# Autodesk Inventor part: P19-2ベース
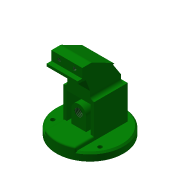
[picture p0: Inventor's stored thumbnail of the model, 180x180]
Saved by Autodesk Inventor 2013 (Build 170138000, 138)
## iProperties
Created: 2008-07
Part Number: P19-2ベース
Document SubType Name: Modeling
Designer: y-shimohigashi
Density: 1 g/cm^3
Stock Number: P19-2ベース
Material: 一般
Author: y-shimohigashi
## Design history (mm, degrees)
sketch "スケッチ2"
  geometry: C1 r 65 at (0, 0); 1 further point
  constraints: 1 centre point, 1 coincident
  dimensions: "d0" = 130 diameter of C1
extrude "押し出し1" new body sketch "スケッチ2" distance "d1" = 15; taper "d2" = 0 deg
sketch "スケッチ3"
  geometry: L1 (-65, 15)-(65, 15) reference; L2 (43, 15)-(43, 80); L3 (43, 80)-(38, 80); L4 (38, 80)-(38, 93); L5 (38, 93)-(16, 127); L6 (16, 127)-(-27, 149); L7 (-27, 149)-(-45, 149); L8 (-45, 149)-(-45, 131); L9 (-45, 131)-(-54, 131); L10 (-54, 131)-(-54, 126); L11 (-54, 126)-(-44, 126); L12 (-44, 126)-(-31, 119); L13 (-31, 119)-(-22, 95); L14 (-22, 95)-(-22, 15); L15 (-22, 15)-(43, 15); 1 further point
  constraints: 28 end point, 6 parallel, 3 perpendicular, 2 point on line, 1 collinear
  dimensions: "d3" = 43 distance from line of L2 point (0, 0); "d4" = 65 distance of L2.start L2.end; "d5" = 13 distance of L3.end L4.end; "d6" = 34 vertical distance of L4.end L5.end; "d7" = 22 vertical distance of L5.end L6.end; "d8" = 5 distance of L2.end L3.end; "d9" = 22 horizontal distance of L4.end L5.end; "d10" = 43 horizontal distance of L5.end L6.end; "d11" = 18 distance of L6.end L7.end; "d12" = 9 distance of L8.end L9.end; "d13" = 18 distance of L7.end L8.end; "d14" = 5 distance of L9.end L10.end; "d15" = 10 distance of L10.end L11.end; "d16" = 24 vertical distance of L12.end L13.end; "d17" = 80 distance of L13.end L14.end; "d18" = 65 distance between parallel lines of L2 L14; "d19" = 13 horizontal distance of L11.end L12.end
extrude "押し出し2" join sketch "スケッチ3" stored distance "d20" = 60; taper "d21" = 0 deg
sketch "スケッチ4"
  geometry: L1 (0, 0)-(60, 0) reference; L2 (60, 0)-(52, 0); L3 (52, 0)-(52, -45); L4 (52, -45)-(60, -45); L5 (60, -45)-(60, 0); L6 (0, 0)-(8, 0); L7 (8, 0)-(8, -45); L8 (8, -45)-(0, -45); L9 (0, -45)-(0, 0)
  constraints: 16 end point, 4 parallel, 2 collinear, 2 horizontal, 2 perpendicular
  dimensions: "d22" = 8 distance of L3.end L4.end; "d23" = 45 distance of L4.end L1.end
extrude "押し出し3" cut sketch "スケッチ4" stored distance "d24" = 60; taper "d25" = 0 deg
sketch "スケッチ5"
  geometry: L1 (60, -65)-(60, 0) reference; L2 (0, 0)-(60, 0) reference; L3 (0, 0)-(0, -65) reference; L4 (0, -65)-(60, -65) reference; L5 (53, -58)-(53, -7); L6 (53, -7)-(7, -7); L7 (7, -7)-(7, -58); L8 (7, -58)-(53, -58); L9 (44.5, -7)-(44.5, -32.5); L10 (15.5, -32.5)-(15.5, -7); A1 r 14.5 centre (30, -32.5) between (15.5, -32.5) and (44.5, -32.5); 2 further points
  constraints: 12 end point, 2 midpoint, 2 perpendicular, 2 point on circle, 2 point on line, 2 tangent, 1 centre point, 1 horizontal alignment, 1 vertical alignment, 3 other
  dimensions: "d26" = 7 distance between parallel lines of L3 L7; "d27" = 8.5 distance between parallel lines of L7 L10
extrude "押し出し4" cut sketch "スケッチ5" stored distance "d28" = 60; taper "d29" = 0 deg
hole "穴1" diameter "d32" = 15.294; stored, may be unused: countersink angle "d36" = 90 deg, drill point angle "d38" = 118 deg; dims "d30" = 10, "d31" = 10, "d33" = 6, "d34" = 4, "d35" = 2, "d37" = 8
sketch "スケッチ6"
  geometry: L1 (30, -22)-(-30, -22) reference; L2 (-30, -22)-(-30, -57.663); L3 (30, -22)-(30, -57.663); A1 r 65 centre (0, 0) between (-30, -57.663) and (30, -57.663) reference; A2 r 65 centre (0, 0) between (-30, -57.663) and (30, -57.663)
  constraints: 4 end point, 4 point on circle, 1 centre point, 1 concentric, 1 parallel, 1 perpendicular
extrude "押し出し5" join sketch "スケッチ6" stored distance "d39" = 60; taper "d40" = 0 deg
sketch "スケッチ7" dims "d41" = 106
  geometry: 3 further points
  constraints: 2 vertical alignment, 1 coincident, 2 other
hole "穴2" sketch "スケッチ7" at (0, 53) diameter "d42" = 8; stored, may be unused: countersink angle "d46" = 90 deg, drill point angle "d48" = 118 deg; dims "d43" = 6, "d44" = 4, "d45" = 2, "d47" = 8
pattern_circular "放射状パターン1" dims angle "d50" = 360 deg
sketch "スケッチ8"
  geometry: L1 (30, -178.8)-(30, 29.8) reference; L2 (60, -18)-(60, 0) reference; 3 further points
  constraints: 1 horizontal alignment, 1 midpoint, 1 symmetric about line
  dimensions: "d53" = 30 distance of point (15, -9) point (45, -9)
hole "穴3" sketch "スケッチ8" at (15, -9), (45, -9) diameter "d54" = 6.647; stored, may be unused: countersink angle "d58" = 90 deg, drill point angle "d60" = 118 deg; dims "d55" = 6, "d56" = 4, "d57" = 2, "d59" = 8
fillet "フィレット1" dims "d52" = 8
fillet "フィレット2" dims "d61" = 8
fillet "フィレット3" dims "d62" = 3
chamfer "面取り1" distance "d63" = 3; stored, may be unused: second distance "d64" = 2, angle "d65" = 45 deg
node "ソリッド1"
node "ソリッド ボディ"
node "サーフェス ボディ"
node "投影ループ1"
